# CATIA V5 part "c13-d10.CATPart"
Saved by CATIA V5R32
Part number: Part1
Bounding box of the stored display mesh (mm): x -49.986 to 49.986, y -49.986 to 49.986, z 0 to 320
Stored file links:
  D:\PROJECTS\Project 2022\CATIA V5 6R 2022\Resources\Part Files\c13_catia_v5_6r2022_prt\c13_catia_v5-6r2022_figr_13-39 & 40\c13-d10.CATPart
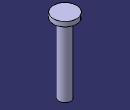
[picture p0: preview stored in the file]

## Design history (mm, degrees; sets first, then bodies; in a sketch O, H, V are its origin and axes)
Body1 (main body)
  Sketch1 on yz-plane, origin (0, 0, 0), H (0, 1, 0), V (0, 0, 1)
    axis line L1 (0, 0) -> (0, 409.3493)
    line L2 (0, 0) -> (25, 0)
    line L3 (25, 0) -> (25, 300)
    line L4 (25, 300) -> (50, 300)
    line L5 (50, 300) -> (50, 320)
    line L6 (50, 320) -> (0, 320)
    point P6 (0, 320)
    line L7 (0, 320) -> (0, 0)
    radius about axis L5 L1 = 50
    radius about axis L3 L1 = 25
    length L3 = 300
    length L5 = 20
    vertical: L1 V, L3 V, L5 V, L7 V
    horizontal: L2 H, L4 H, L6 H
    coincidence: P6 L1
  Shaft1: profile Sketch1, axis Sketch1.L1, angle 360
